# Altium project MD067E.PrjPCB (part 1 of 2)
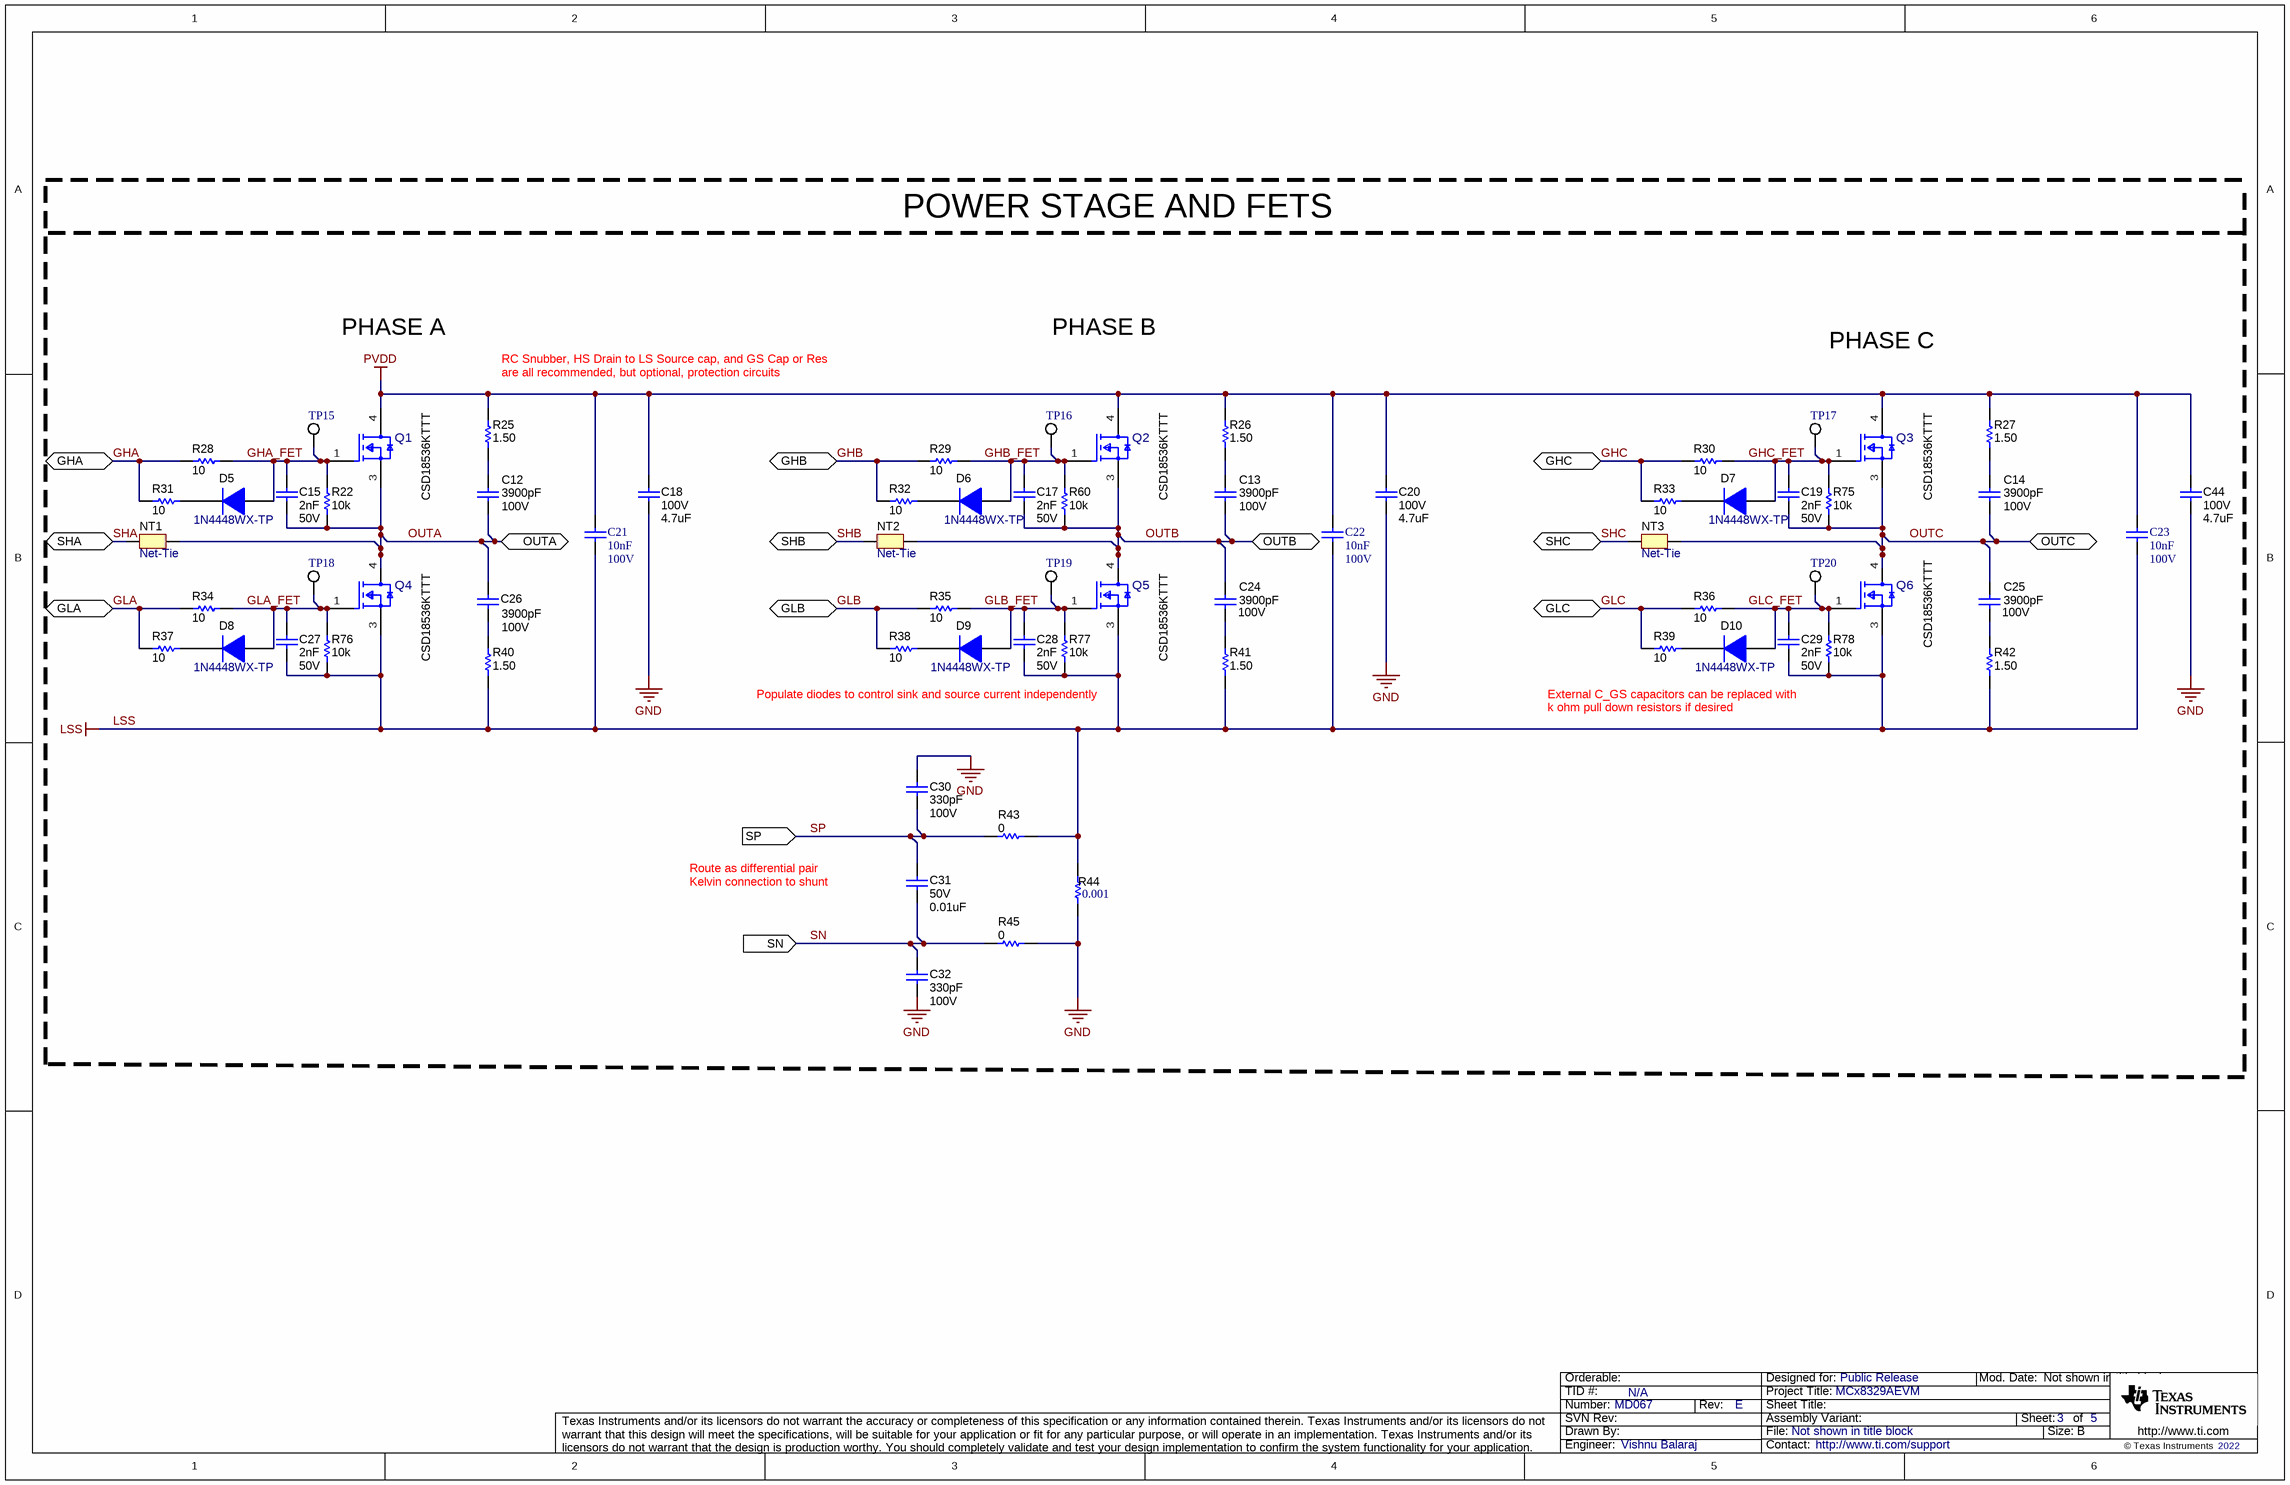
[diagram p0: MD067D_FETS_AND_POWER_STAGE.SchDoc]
TID: N/A; TechSupport: http://www.ti.com/support; SCH_Rev: E; PRJ_Title: MCx8329AEVM; PRJ_Number: MD067; PRJ_Engineer: Vishnu Balaraj; PRJ_Customer: Public Release; PCB_Rev: D; PCB_Layout: Vishnu Balaraj; CopyrightYear: 2022
5 sheets, 235 parts. Net scope: flat (ports and power ports of the same name join across sheets).
Board file: MD067D.PcbDoc
Sheets:
  MD067D_FETS_AND_POWER_STAGE.SchDoc
  MD067D_DRIVER.SchDoc
  MD067D_INTERFACE.SchDoc
  MD067D_HARDWARE.SchDoc
  MD067D_POWER_AND_CONNECTORS.SchDoc

## Sheet MD067D_FETS_AND_POWER_STAGE.SchDoc
size 431 x 279 mm; Date: Not shown in title block; ApprovedBy: Not shown in title block; CheckedBy: Not shown in title block; Author: Not shown in title block; CompanyName: Not shown in title block; Engineer: Not shown in title block; Organization: Not shown in title block; Address1: Not shown in title block; Address2: Not shown in title block; Address3: Not shown in title block; Address4: Not shown in title block; DocumentNumber: 3; Revision: Use project parameter SCH_Rev; SheetNumber: 3; SheetTotal: 5; PageSetup: Record=PageOptions¦CenterHorizontal=True¦CenterVertical=True¦PrintScale=1.00¦XCorrection=1.00¦YCorrection=1.00¦PrintKind=0¦BorderSize=5000000¦LeftOffset=0¦BottomOffset=0¦Orientation=2¦PaperLength=1000¦PaperWidth=1000¦Scale=100¦PaperSource=15¦PrintQuality=600¦MediaType=1¦DitherType=10¦PaperKind=Letter¦PrintScaleMode=1

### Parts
C12  VDC_V: 100V  ValueDisplayed: 3900pF  [1206L]  (hidden comment: 12061C392KAZ2A)
C13  VDC_V: 100V  ValueDisplayed: 3900pF  [1206L]  (hidden comment: 12061C392KAZ2A)
C14  VDC_V: 100V  ValueDisplayed: 3900pF  [1206L]  (hidden comment: 12061C392KAZ2A)
C15  Cap_F: 2nF  VDC_V: 50V  [0603L]  (hidden comment: GRM188R71H202KA01D)  (no BOM)
C17  Cap_F: 2nF  VDC_V: 50V  [0603L]  (hidden comment: GRM188R71H202KA01D)  (no BOM)
C18  VDC_V: 100V  ValueDisplayed: 4.7uF  [1210_220L]  (hidden comment: GRM32DC72A475KE01L)
C19  Cap_F: 2nF  VDC_V: 50V  [0603L]  (hidden comment: GRM188R71H202KA01D)  (no BOM)
C20  VDC_V: 100V  ValueDisplayed: 4.7uF  [1210_220L]  (hidden comment: GRM32DC72A475KE01L)
C21  Cap_F: 10nF  Rated Voltage (DC): 100V  [WCAP-CSGP_0805_L2W1.25H0.8_Reflow]  (hidden comment: 885012207122)
C22  Cap_F: 10nF  Rated Voltage (DC): 100V  [WCAP-CSGP_0805_L2W1.25H0.8_Reflow]  (hidden comment: 885012207122)
C23  Cap_F: 10nF  Rated Voltage (DC): 100V  [WCAP-CSGP_0805_L2W1.25H0.8_Reflow]  (hidden comment: 885012207122)
C24  VDC_V: 100V  ValueDisplayed: 3900pF  [1206L]  (hidden comment: 12061C392KAZ2A)
C25  VDC_V: 100V  ValueDisplayed: 3900pF  [1206L]  (hidden comment: 12061C392KAZ2A)
C26  VDC_V: 100V  ValueDisplayed: 3900pF  [1206L]  (hidden comment: 12061C392KAZ2A)
C27  Cap_F: 2nF  VDC_V: 50V  [0603L]  (hidden comment: GRM188R71H202KA01D)  (no BOM)
C28  Cap_F: 2nF  VDC_V: 50V  [0603L]  (hidden comment: GRM188R71H202KA01D)  (no BOM)
C29  Cap_F: 2nF  VDC_V: 50V  [0603L]  (hidden comment: GRM188R71H202KA01D)  (no BOM)
C30  Cap_F: 330pF  VDC_V: 100V  [0603L]  (hidden comment: 06031C331KAT2A)
C31  VDC_V: 50V  ValueDisplayed: 0.01uF  [0603L]  (hidden comment: C1608NP01H103J080AA)
C32  Cap_F: 330pF  VDC_V: 100V  [0603L]  (hidden comment: 06031C331KAT2A)
C44  VDC_V: 100V  ValueDisplayed: 4.7uF  [1210_220L]  (hidden comment: GRM32DC72A475KE01L)
D5  1N4448WX-TP  [SOD-323]
D6  1N4448WX-TP  [SOD-323]
D7  1N4448WX-TP  [SOD-323]
D8  1N4448WX-TP  [SOD-323]
D9  1N4448WX-TP  [SOD-323]
D10  1N4448WX-TP  [SOD-323]
NT1  Net-Tie  [Net-Tie_0805_HV_NoOverlay]  (net tie, no BOM)
NT2  Net-Tie  [Net-Tie_0805_HV_NoOverlay]  (net tie, no BOM)
NT3  Net-Tie  [Net-Tie_0805_HV_NoOverlay]  (net tie, no BOM)
Q1  CSD18536KTTT  [KTT0002A-MFG]
Q2  CSD18536KTTT  [KTT0002A-MFG]
Q3  CSD18536KTTT  [KTT0002A-MFG]
Q4  CSD18536KTTT  [KTT0002A-MFG]
Q5  CSD18536KTTT  [KTT0002A-MFG]
Q6  CSD18536KTTT  [KTT0002A-MFG]
R22  ValueDisplayed: 10k  [0603L]  (hidden comment: CRCW060310K0JNEA)
R25  ValueDisplayed: 1.50  [1206L]  (hidden comment: CRCW12061R50FKEA)
R26  ValueDisplayed: 1.50  [1206L]  (hidden comment: CRCW12061R50FKEA)
R27  ValueDisplayed: 1.50  [1206L]  (hidden comment: CRCW12061R50FKEA)
R28  ValueDisplayed: 10  [0603L]  (hidden comment: CRCW060310R0JNEA)
R29  ValueDisplayed: 10  [0603L]  (hidden comment: CRCW060310R0JNEA)
R30  ValueDisplayed: 10  [0603L]  (hidden comment: CRCW060310R0JNEA)
R31  ValueDisplayed: 10  [0603L]  (hidden comment: CRCW060310R0JNEA)
R32  ValueDisplayed: 10  [0603L]  (hidden comment: CRCW060310R0JNEA)
R33  ValueDisplayed: 10  [0603L]  (hidden comment: CRCW060310R0JNEA)
R34  ValueDisplayed: 10  [0603L]  (hidden comment: CRCW060310R0JNEA)
R35  ValueDisplayed: 10  [0603L]  (hidden comment: CRCW060310R0JNEA)
R36  ValueDisplayed: 10  [0603L]  (hidden comment: CRCW060310R0JNEA)
R37  ValueDisplayed: 10  [0603L]  (hidden comment: CRCW060310R0JNEA)
R38  ValueDisplayed: 10  [0603L]  (hidden comment: CRCW060310R0JNEA)
R39  ValueDisplayed: 10  [0603L]  (hidden comment: CRCW060310R0JNEA)
R40  ValueDisplayed: 1.50  [1206L]  (hidden comment: CRCW12061R50FKEA)
R41  ValueDisplayed: 1.50  [1206L]  (hidden comment: CRCW12061R50FKEA)
R42  ValueDisplayed: 1.50  [1206L]  (hidden comment: CRCW12061R50FKEA)
R43  ValueDisplayed: 0  [0603L]  (hidden comment: ERJ-3GEY0R00V)
R44  ValueDisplayed: 0.001  [CRE2512-R1_R4]  (hidden comment: CRE2512-FZ-R001E-3)
R45  ValueDisplayed: 0  [0603L]  (hidden comment: ERJ-3GEY0R00V)
R60  ValueDisplayed: 10k  [0603L]  (hidden comment: CRCW060310K0JNEA)
R75  ValueDisplayed: 10k  [0603L]  (hidden comment: CRCW060310K0JNEA)
R76  ValueDisplayed: 10k  [0603L]  (hidden comment: CRCW060310K0JNEA)
R77  ValueDisplayed: 10k  [0603L]  (hidden comment: CRCW060310K0JNEA)
R78  ValueDisplayed: 10k  [0603L]  (hidden comment: CRCW060310K0JNEA)
TP15  GHA_FET  [Testpoint_Keystone_Miniature]  (value not drawn)
TP16  GHB_FET  [Testpoint_Keystone_Miniature]  (value not drawn)
TP17  GHC_FET  [Testpoint_Keystone_Miniature]  (value not drawn)
TP18  GLA_FET  [Testpoint_Keystone_Miniature]  (value not drawn)
TP19  GLB_FET  [Testpoint_Keystone_Miniature]  (value not drawn)
TP20  GLC_FET  [Testpoint_Keystone_Miniature]  (value not drawn)

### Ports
GHA (bidir), GHB (bidir), GHC (bidir), GLA (bidir), GLB (bidir), GLC (bidir), OUTA (bidir), OUTB (bidir), OUTC (bidir), SHA (bidir), SHB (bidir), SHC (bidir), SN (in), SP (in)

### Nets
GND: C18.2 C20.2 C30.1 C32.2 C44.2 R44.1 R45.2
LSS: C21.1 C22.1 C23.1 C27.2 C28.2 C29.2 Q4.3(Source) Q5.3(Source) Q6.3(Source) R40.1 R41.1 R42.1 R43.2 R44.2 R76.1 R77.1 R78.1
PVDD: C18.1 C20.1 C21.2 C22.2 C23.2 C44.1 Q1.4(Drain) Q2.4(Drain) Q3.4(Drain) R25.1 R26.1 R27.1
GHA: R28.1 R31.1 ; port GHA
GHA_FET: C15.1 D5.2(A) Q1.1(Gate) R22.2 R28.2 TP15.1
GHB: R29.1 R32.1 ; port GHB
GHB_FET: C17.1 D6.2(A) Q2.1(Gate) R29.2 R60.2 TP16.1
GHC: R30.1 R33.1 ; port GHC
GHC_FET: C19.1 D7.2(A) Q3.1(Gate) R30.2 R75.2 TP17.1
GLA: R34.1 R37.1 ; port GLA
GLA_FET: C27.1 D8.2(A) Q4.1(Gate) R34.2 R76.2 TP18.1
GLB: R35.1 R38.1 ; port GLB
GLB_FET: C28.1 D9.2(A) Q5.1(Gate) R35.2 R77.2 TP19.1
GLC: R36.1 R39.1 ; port GLC
GLC_FET: C29.1 D10.2(A) Q6.1(Gate) R36.2 R78.2 TP20.1
OUTA: C12.1 C15.2 C26.1 NT1.2 Q1.3(Source) Q4.4(Drain) R22.1 ; port OUTA
OUTB: C13.1 C17.2 C24.1 NT2.2 Q2.3(Source) Q5.4(Drain) R60.1 ; port OUTB
OUTC: C14.1 C19.2 C25.1 NT3.2 Q3.3(Source) Q6.4(Drain) R75.1 ; port OUTC
SHA: NT1.1 ; port SHA
SHB: NT2.1 ; port SHB
SHC: NT3.1 ; port SHC
SN: C31.2 C32.1 R45.1 ; port SN
SP: C30.2 C31.1 R43.1 ; port SP
NetC12_2: C12.2 R25.2
NetC13_2: C13.2 R26.2
NetC14_2: C14.2 R27.2
NetC24_2: C24.2 R41.2
NetC25_2: C25.2 R42.2
NetC26_2: C26.2 R40.2
NetD5_1: D5.1(K) R31.2
NetD6_1: D6.1(K) R32.2
NetD7_1: D7.1(K) R33.2
NetD8_1: D8.1(K) R37.2
NetD9_1: D9.1(K) R38.2
NetD10_1: D10.1(K) R39.2

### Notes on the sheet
- POWER STAGE AND FETS
- PHASE A
- RC Snubber, HS Drain to LS Source cap, and GS Cap or Res
- PHASE B
- PHASE C
- (near R25) are all recommended, but optional, protection circuits
- Populate diodes to control sink and source current independently
- External C_GS capacitors can be replaced with
- k ohm pull down resistors if desired
- Route as differential pair
- Kelvin connection to shunt

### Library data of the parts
C12-C14 C24-C26 = CMP-0008756-2: CAP CER 3900PF 100V X7R 1206; Manufacturer: AVX Corporation; TaMin_C: -55°C; Polarized: N; SizeAreaWB_mm2: 10.92; Value1: Unknown; U/M: EA; TaMax_C: 125°C; Tolerance_%: 10%; SizeZ_mm: 1.35; SizeX_mm: 3.2; SizeY_mm: 1.6; Cap_Case: 1206; SizeArea_mm2: 5.12; Cap_F: 3.9nF; AEC Category: Q200
C15 C17 C19 C27-C29 = CMP-0007441-5: CAP, CERM, 2000 pF, 50 V, +/- 10%, X7R, 0603; Manufacturer: MuRata; TaMin_C: -55°C; Polarized: N; SizeAreaWB_mm2: 4.68; Value1: Unknown; U/M: EA; Value: 2000pF; TaMax_C: 125°C; SizeZ_mm: 1; SizeX_mm: 1.6; SizeY_mm: 0.8; Cap_Case: 0603; SizeArea_mm2: 1.28; AEC Category: Q200
C18 C20 C44 = CMP-0009182-2: CAP, CERM, 4.7 uF, 100 V, +/- 10%, X7S, 1210; Manufacturer: MuRata; TaMin_C: -55°C; Polarized: N; SizeAreaWB_mm2: 14.7; Value1: Unknown; U/M: EA; Value: 4.7uF; TaMax_C: 125°C; SizeZ_mm: 2.2; SizeX_mm: 3.2; SizeY_mm: 2.5; Cap_Case: 1210; SizeArea_mm2: 8; Cap_F: 4.7µF; AEC Category: Q200
C21-C23 = CMP-0108439-1: WCAP-CSGP Multilayer Ceramic Chip Capacitor, General Purpose, size 0805, X7R, 10nF, 100VDC; Manufacturer: Wurth Elektronik; Capacitance Tolerance: +/-10%; Case/Size Code: 0805; Dissipation Factor: 2.5%; Insulation Resistance: 10GOhm; Technical Reference: X7R0805103K100DFCT10000; Value: 0.01uF
C30 C32 = CMP-0006740-4: CAP, CERM, 330 pF, 100 V, +/- 10%, X7R, 0603; Manufacturer: AVX; TaMin_C: -55°C; ESR_ohm: 0.472; Polarized: N; SizeAreaWB_mm2: 4.68; Value1: 0.472 ohm; U/M: EA; Value: 330pF; TaMax_C: 125°C; SizeZ_mm: 1; SizeX_mm: 1.6; SizeY_mm: 0.8; Cap_Case: 0603; SizeArea_mm2: 1.28; AEC Category: Q200
C31 = CMP-0006998-4: CAP, CERM, 0.01 uF, 50 V, +/- 5%, C0G/NP0, 0603; Manufacturer: TDK; TaMin_C: -55°C; Polarized: N; SizeAreaWB_mm2: 4.68; Value1: Unknown; U/M: EA; Value: 0.01uF; TaMax_C: 150°C; SizeZ_mm: 1; SizeX_mm: 1.6; SizeY_mm: 0.8; Cap_Case: 0603; SizeArea_mm2: 1.28; Cap_F: 10nF; AEC Category: Q200
D5-D10 = CMP-0076911-2: Diode, Switching, 75 V, 0.25 A, SOD-323; Manufacturer: Micro Commercial Components; SizeArea_mm2: 3.645; TJmax_C: 150°C; Vr_V: 75V; SizeY_mm: 1.35; Value: 75V; SizeAreaWB_mm2: 8.695; Green_Lifecycle: Not Set; SizeX_mm: 2.7; AEC Category: Q101; Io_A: 250mA; Green_REACh: Incomplete; Value1: 0.25A; SizeZ_mm: 1.0
NT1-NT3 = CMP-0078142-2: Single point connection between nets.
Q1-Q6 = CMP-0092295-1: MOSFET 60-V, N channel NexFET power MOSFET, single D2PAK, 1.6 mOhm 3-DDPAK/TO-263 -55 to 175; Manufacturer: Texas Instruments; QgTyp_nC: 108nC @ 10V; Threshold Vgs Min: 1.4V; VdsMax_V: 1V; Standoff Height: 0mm; Rdson45_ohm: 1.3m; Reverse Recovery Time: 86ns; ChMode: False; Turn On Delay Time: 11ns; Typ Forward Diode Voltage: 0.9V; Transconductance: 312S; Threshold Vgs Max: 2.2V; Rthja Max: 62°C/W; Drain To Source Breakdown Voltage: 60V; Reverse Recovery Charge: 323nC; TJmax_C: +175°C; AEC Qualified: No; Power_W: 375W; Turn Off Delay Time: 24ns; Number Of Channels: 1; Vgs_V: 20V; SizeZ_mm: 4.95mm; Pulse Drain Current: 400A; IdsMax_A: 200A; Input Capacitace At Vds: 8790pF @ 30V
R22 R60 R75-R78 = CMP-0025701-2: RES, 10 k, 5%, 0.1 W, 0603; Manufacturer: Vishay-Dale; Power_W: 100mW; TempCo: 200 ppm/C; Value_Code: 10k0; U/M: EA; Value: 10k; EIA_Code: E24; SizeX_mm: 1.6; SizeY_mm: 0.8; SizeZ_mm: 1; Value2: 0.1W; SizeArea_mm2: 1.28; VDC_V: 75V; AEC Category: Q200
R25-R27 R40-R42 = CMP-0016763-3: RES, 1.50, 1%, 0.25 W, AEC-Q200 Grade 0, 1206; Manufacturer: Vishay-Dale; Power_W: 250mW; TempCo: 100 ppm/C; Value_Code: 1R50; Value: 1.50; EIA_Code: E96; Res_ohm: 1.5; SizeX_mm: 3.2; SizeY_mm: 1.6; SizeZ_mm: 1.35; Value2: 0.25W; SizeArea_mm2: 5.12; AEC Qualified: Y; VDC_V: 200V; AEC Category: Q200; AEC Grade: 0
R28-R39 = CMP-0025703-4: RES, 10, 5%, 0.1 W, AEC-Q200 Grade 0, 0603; Manufacturer: Vishay-Dale; Power_W: 100mW; TempCo: 200 ppm/C; Value_Code: 10R0; Value: 10; EIA_Code: E24; SizeX_mm: 1.6; SizeY_mm: 0.8; SizeZ_mm: 1; Value2: 0.1W; SizeArea_mm2: 1.28; AEC Qualified: Y; VDC_V: 75V; AEC Category: Q200; AEC Grade: 0
R43 R45 = CMP-0025874-4: RES, 0, 5%, 0.1 W, AEC-Q200 Grade 0, 0603; Manufacturer: Panasonic; Power_W: 100mW; TempCo: 600 ppm/C; Value_Code: 0000; Value: 0; EIA_Code: E24; SizeX_mm: 1.6; SizeY_mm: 0.8; SizeZ_mm: 1; Value2: 0.1W; SizeArea_mm2: 1.28; AEC Qualified: Y; VDC_V: 50V; AEC Category: Q200; SizeAreaWB_mm2: 4.68
R44 = CMP-0015748-2: RES, 0.001, 1%, 3 W, AEC-Q200 Grade 0, 2512; Manufacturer: Bourns; Power_W: 3W; TempCo: 50 ppm/C; Value_Code: 1L000; U/M: EA; Value: 0.001; EIA_Code: E96; Res_ohm: 1m; SizeX_mm: 6.45; SizeY_mm: 3.35; SizeZ_mm: 0.9; SizeArea_mm2: 21.6075; AEC Qualified: Y; AEC Grade: 0; AEC Category: Q200
TP15-TP20 = CMP-0055152-1: Test Point, Miniature, SMT; Manufacturer: Keystone; CNHeader: FALSE; Green_Lifecycle: Active; Green_REACh: Passed; CT: TRUE

## Sheet MD067D_DRIVER.SchDoc
size 431 x 279 mm; Date: Not shown in title block; ApprovedBy: Not shown in title block; CheckedBy: Not shown in title block; Author: Not shown in title block; CompanyName: Not shown in title block; Engineer: Not shown in title block; Organization: Not shown in title block; Address1: Not shown in title block; Address2: Not shown in title block; Address3: Not shown in title block; Address4: Not shown in title block; DocumentNumber: 2; Revision: Use project parameter SCH_Rev; SheetNumber: 2; SheetTotal: 5; PageSetup: Record=PageOptions¦CenterHorizontal=True¦CenterVertical=True¦PrintScale=1.00¦XCorrection=1.00¦YCorrection=1.00¦PrintKind=0¦BorderSize=5000000¦LeftOffset=0¦BottomOffset=0¦Orientation=2¦PaperLength=1000¦PaperWidth=1000¦Scale=100¦PaperSource=15¦PrintQuality=600¦MediaType=1¦DitherType=10¦PaperKind=Letter¦PrintScaleMode=1
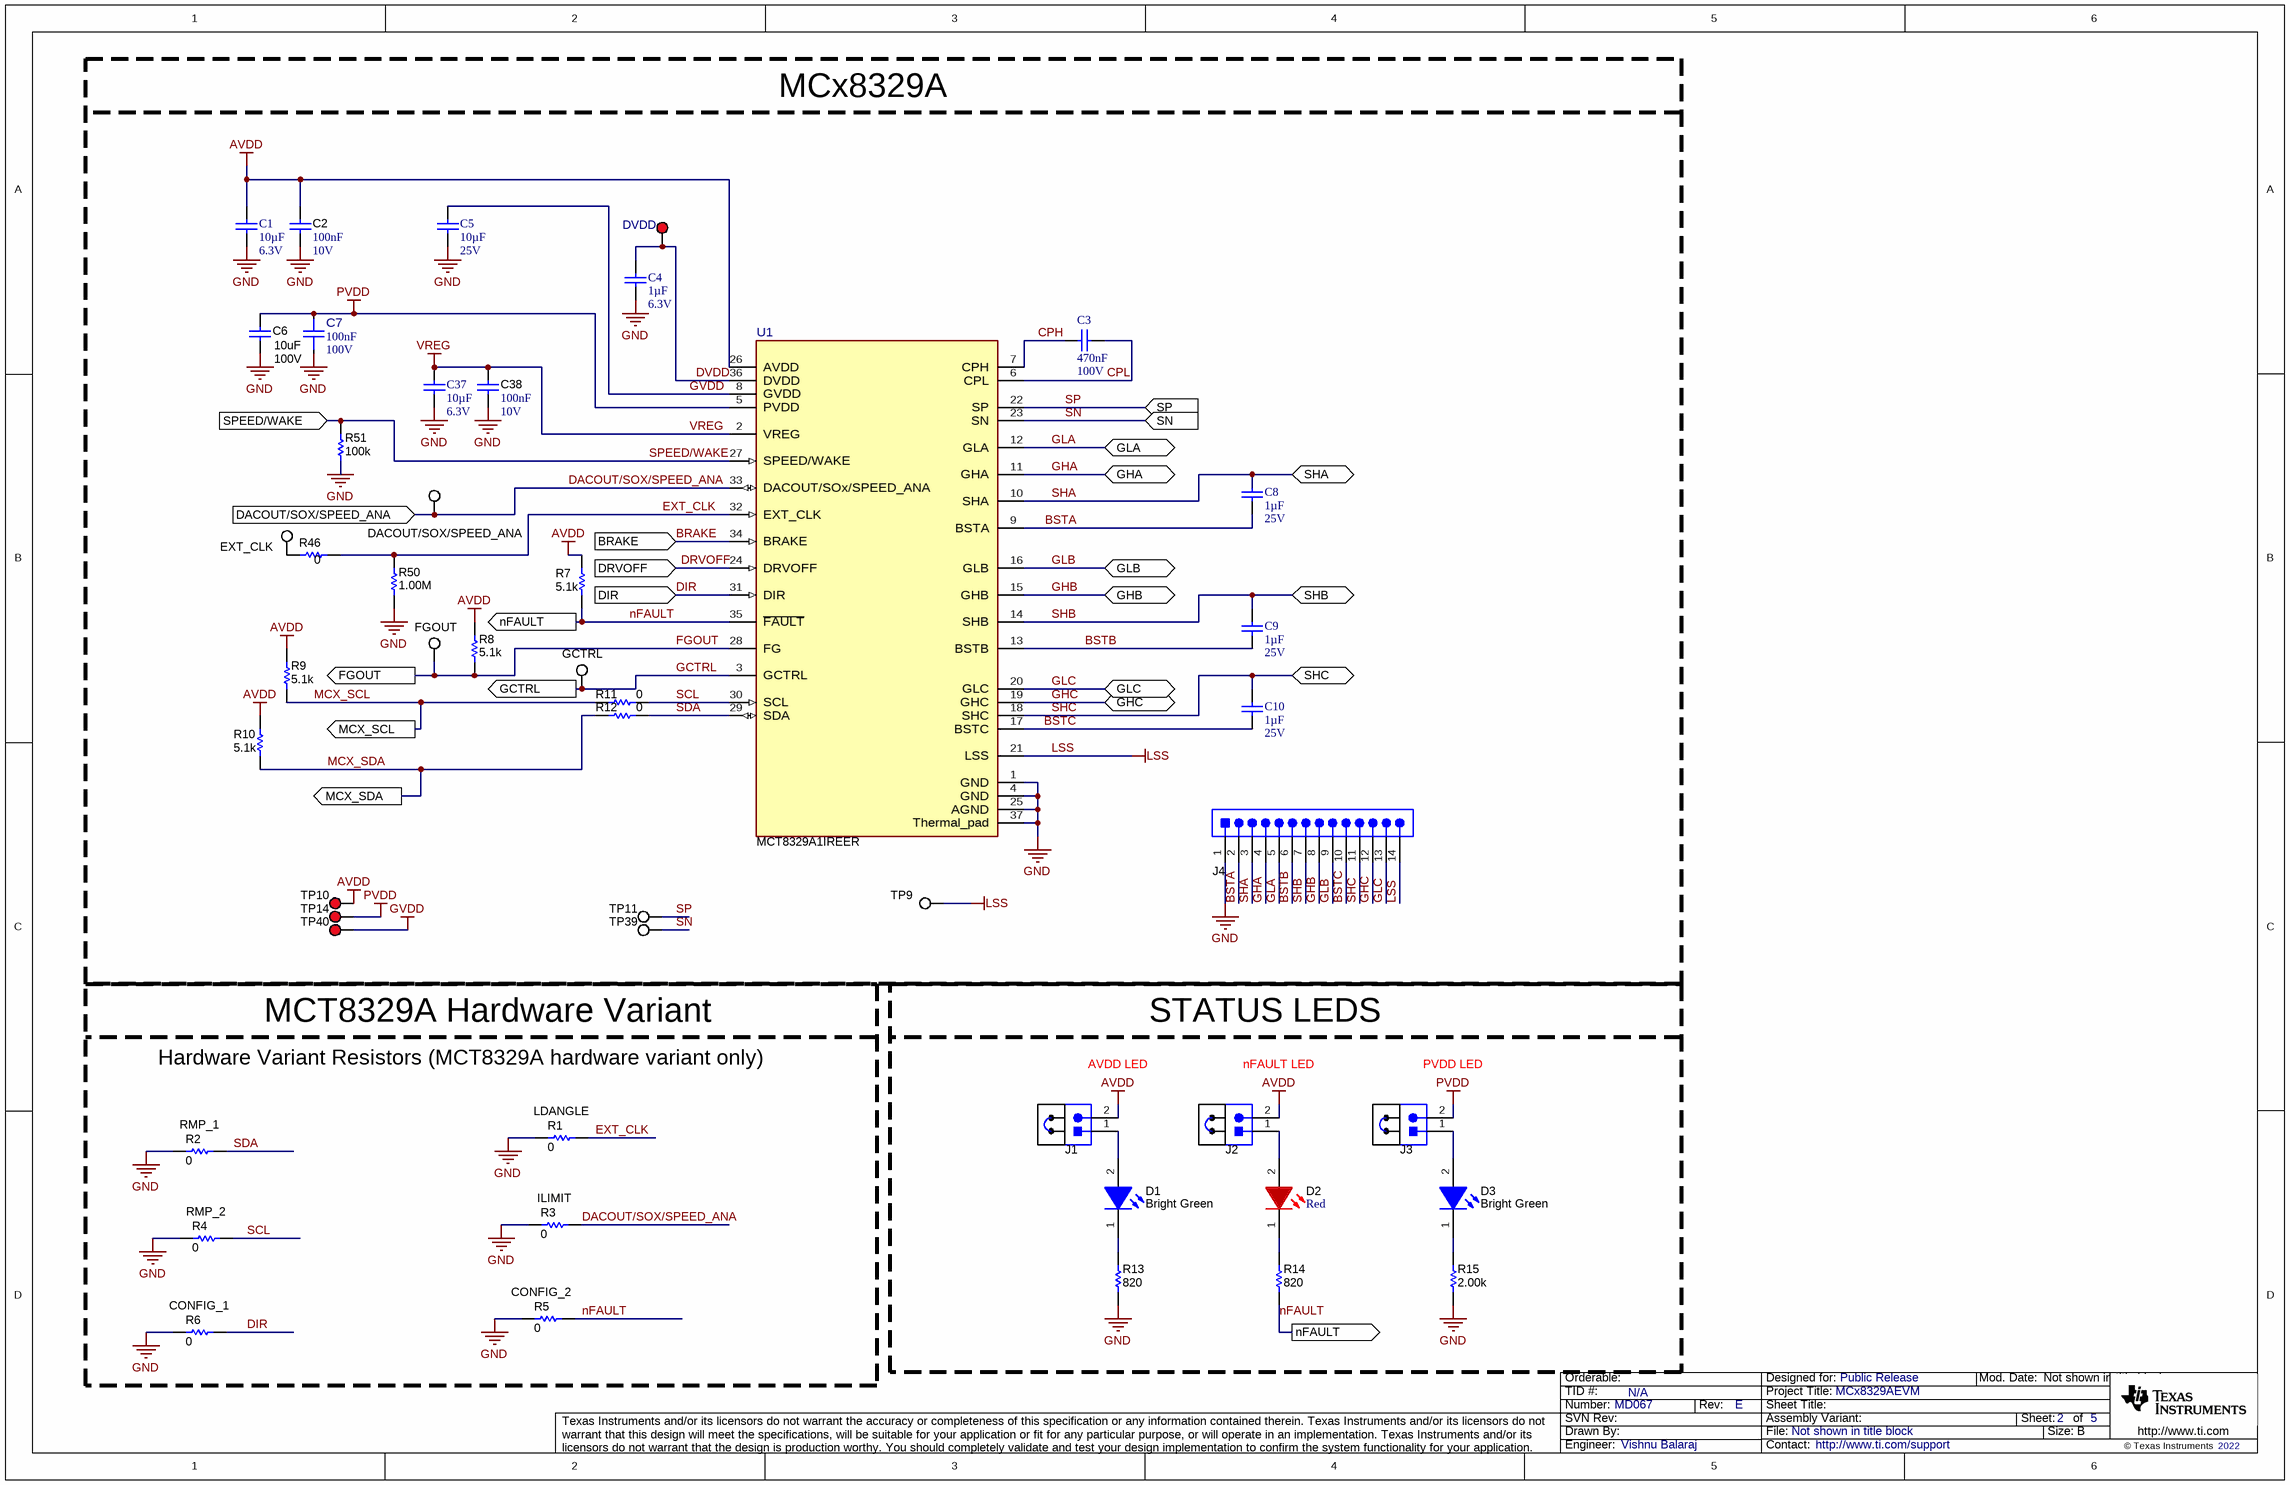
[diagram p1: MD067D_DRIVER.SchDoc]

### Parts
C1  Cap_F: 10µF  Rated Voltage (DC): 6.3V  [WCAP-CSGP_0603_L1.6W0.8H0.8_Reflow]  (hidden comment: 885012106006)
C2  Cap_F: 100nF  VDC_V: 10V  [0603]  (hidden comment: 885012206020)
C3  Cap_F: 470nF  Rated Voltage (DC): 100V  [WCAP-CSGP_0805_L2W1.25H1.25]  (hidden comment: 885012207130)
C4  Cap_F: 1µF  Rated Voltage (DC): 6.3V  [WCAP-CSGP_0603_L1.6W0.8H0.8_Reflow]  (hidden comment: 885012106003)
C5  Cap_F: 10µF  Rated Voltage (DC): 25V  [WCAP-CSGP_0603_L1.6W0.8H0.8_Reflow]  (hidden comment: 885012106031)
C6  VDC_V: 100V  ValueDisplayed: 10uF  [2220_280L]  (hidden comment: 22201C106MAT2A)
C7  Cap_F: 100nF  VDC_V: 100V  [FP-885012206120_0603-MFG]  (hidden comment: 885012206120)
C8  Cap_F: 1µF  Rated Voltage (DC): 25V  [WCAP-CSGP_0603_L1.6W0.8H0.8_Reflow]  (hidden comment: 885012106022)
C9  Cap_F: 1µF  Rated Voltage (DC): 25V  [WCAP-CSGP_0603_L1.6W0.8H0.8_Reflow]  (hidden comment: 885012106022)
C10  Cap_F: 1µF  Rated Voltage (DC): 25V  [WCAP-CSGP_0603_L1.6W0.8H0.8_Reflow]  (hidden comment: 885012106022)
C37  Cap_F: 10µF  Rated Voltage (DC): 6.3V  [WCAP-CSGP_0603_L1.6W0.8H0.8_Reflow]  (hidden comment: 885012106006)
C38  Cap_F: 100nF  VDC_V: 10V  [0603]  (hidden comment: 885012206020)
D1  value Bright Green  [WL-SMCW_Green_0805]  (hidden comment: 150080VS75000)
D2  value Red  [WL-SMCW_RED_0805]  (hidden comment: 150080RS75000)
D3  value Bright Green  [WL-SMCW_Green_0805]  (hidden comment: 150080VS75000)
J1  61300211121  [WURTH_61300211121]  (value not drawn)
J2  61300211121  [WURTH_61300211121]  (value not drawn)
J3  61300211121  [WURTH_61300211121]  (value not drawn)
J4  TSW-114-07-G-S  [TSW-114-07-G-S]  (value not drawn)
R1  ValueDisplayed: 0  [0603L]  (hidden comment: ERJ-3GEY0R00V)
R2  ValueDisplayed: 0  [0603L]  (hidden comment: ERJ-3GEY0R00V)
R3  ValueDisplayed: 0  [0603L]  (hidden comment: ERJ-3GEY0R00V)
R4  ValueDisplayed: 0  [0603L]  (hidden comment: ERJ-3GEY0R00V)
R5  ValueDisplayed: 0  [0603L]  (hidden comment: ERJ-3GEY0R00V)
R6  ValueDisplayed: 0  [0603L]  (hidden comment: ERJ-3GEY0R00V)
R7  ValueDisplayed: 5.1k  [0603L]  (hidden comment: CRCW06035K10JNEA)
R8  ValueDisplayed: 5.1k  [0603L]  (hidden comment: CRCW06035K10JNEA)
R9  ValueDisplayed: 5.1k  [0603L]  (hidden comment: CRCW06035K10JNEA)
R10  ValueDisplayed: 5.1k  [0603L]  (hidden comment: CRCW06035K10JNEA)
R11  ValueDisplayed: 0  [0603L]  (hidden comment: ERJ-3GEY0R00V)
R12  ValueDisplayed: 0  [0603L]  (hidden comment: ERJ-3GEY0R00V)
R13  ValueDisplayed: 820  [0603L]  (hidden comment: RC0603JR-07820RL)
R14  ValueDisplayed: 820  [0603L]  (hidden comment: RC0603JR-07820RL)
R15  ValueDisplayed: 2.00k  [0603L]  (hidden comment: RG1608P-202-B-T5)
R46  Res_ohm: 0  [0603]  (hidden comment: ERJ-3GEY0R00V)
R50  ValueDisplayed: 1.00M  [0603]  (hidden comment: RMCF0603FG1M00)
R51  ValueDisplayed: 100k  [0603]  (hidden comment: RT0603BRD07100KL)
SH-J1  60900213421  [Wurth_60900213421]  (value not drawn)
SH-J2  60900213421  [Wurth_60900213421]  (value not drawn)
SH-J3  60900213421  [Wurth_60900213421]  (value not drawn)
TP1  DVDD  [Keystone5000]
TP2  DACOUT/SOX/SPEED_ANA  [Keystone5002]
TP3  EXT_CLK  [Keystone5002]
TP4  FGOUT  [Keystone5002]
TP5  GCTRL  [Keystone5002]
TP9  LSS  [Testpoint_Keystone_Miniature]  (value not drawn)
TP10  AVDD  [Keystone5000]  (value not drawn)
TP11  SP  [Testpoint_Keystone_Miniature]  (value not drawn)
TP14  PVDD  [Keystone5000]  (value not drawn)
TP39  SN  [Testpoint_Keystone_Miniature]  (value not drawn)
TP40  GVDD  [Keystone5000]  (value not drawn)
U1  MCT8329A1IREER  [REE0036A-MFG]

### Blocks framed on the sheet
MCx8329A: C1-C10 C37 C38 J4 R7-R12 R46 R50 R51 TP1-TP5 TP9-TP11 TP14 TP39 TP40 U1
MCT8329A Hardware Variant: R1-R6
STATUS LEDS: D1-D3 J1-J3 R13-R15 SH-J1-SH-J3

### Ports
BRAKE (in), DACOUT/SOX/SPEED_ANA (in), DIR (in), DRVOFF (in), FGOUT (out), GCTRL (out), GHA (bidir), GHB (bidir), GHC (bidir), GLA (bidir), GLB (bidir), GLC (bidir), MCX_SCL (out), MCX_SDA (out), nFAULT (out), SHA (bidir), SHB (bidir), SHC (bidir), SN (in), SP (in), SPEED/WAKE (in)

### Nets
AVDD: C1.2 C2.2 J1.2 J2.2 R7.1 R8.2 R9.2 R10.2 TP10.1 U1.26(AVDD)
GND: C1.1 C2.1 C4.1 C5.1 C6.2 C7.1 C37.1 C38.2 J4.1 R1.2 R2.2 R3.2 R4.2 R5.2 R6.2 R13.1 R15.1 R50.1 R51.1 U1.1(GND) U1.4(GND) U1.25(AGND) U1.37(Thermal_pad)
GVDD: C5.2 TP40.1 U1.8(GVDD)
LSS: J4.14 TP9.1 U1.21(LSS)
PVDD: C6.1 C7.2 J3.2 TP14.1 U1.5(PVDD)
VREG: C37.2 C38.1 U1.2(VREG)
BRAKE: U1.34(BRAKE) ; port BRAKE
BSTA: C8.1 J4.2 U1.9(BSTA)
BSTB: C9.2 J4.6 U1.13(BSTB)
BSTC: C10.2 J4.10 U1.17(BSTC)
CPH: C3.2 U1.7(CPH)
CPL: C3.1 U1.6(CPL)
DACOUT/SOX/SPEED_ANA: R3.1 TP2.1 U1.33(DACOUT/SOx/SPEED_ANA) ; port DACOUT/SOX/SPEED_ANA
DIR: R6.1 U1.31(DIR) ; port DIR
DRVOFF: U1.24(DRVOFF) ; port DRVOFF
DVDD: C4.2 TP1.1 U1.36(DVDD)
EXT_CLK: R1.1 R46.2 R50.2 U1.32(EXT_CLK)
FGOUT: R8.1 TP4.1 U1.28(FG) ; port FGOUT
GCTRL: TP5.1 U1.3(GCTRL) ; port GCTRL
GHA: J4.4 U1.11(GHA) ; port GHA
GHB: J4.8 U1.15(GHB) ; port GHB
GHC: J4.12 U1.19(GHC) ; port GHC
GLA: J4.5 U1.12(GLA) ; port GLA
GLB: J4.9 U1.16(GLB) ; port GLB
GLC: J4.13 U1.20(GLC) ; port GLC
MCX_SCL: R9.1 R11.1 ; port MCX_SCL
MCX_SDA: R10.1 R12.1 ; port MCX_SDA
nFAULT: R5.1 R7.2 R14.1 U1.35(~{FAULT}) ; port nFAULT
SCL: R4.1 R11.2 U1.30(SCL)
SDA: R2.1 R12.2 U1.29(SDA)
SHA: C8.2 J4.3 U1.10(SHA) ; port SHA
SHB: C9.1 J4.7 U1.14(SHB) ; port SHB
SHC: C10.1 J4.11 U1.18(SHC) ; port SHC
SN: TP39.1 U1.23(SN) ; port SN
SP: TP11.1 U1.22(SP) ; port SP
SPEED/WAKE: R51.2 U1.27(SPEED/WAKE) ; port SPEED/WAKE
NetD1_1: D1.1(K) R13.2
NetD1_2: D1.2(A) J1.1
NetD2_1: D2.1(K) R14.2
NetD2_2: D2.2(A) J2.1
NetD3_1: D3.1(K) R15.2
NetD3_2: D3.2(A) J3.1
NetR46_1: R46.1 TP3.1

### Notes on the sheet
- Hardware Variant Resistors (MCT8329A hardware variant only)
- (near R1) LDANGLE
- AVDD LED
- nFAULT LED
- PVDD LED
- (near R2) RMP_1
- (near R4) RMP_2
- (near R3) ILIMIT
- (near R6) CONFIG_1
- (near R5) CONFIG_2

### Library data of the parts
C1 = CMP-0108062-1: WCAP-CSGP Multilayer Ceramic Chip Capacitor, General Purpose, size 0603, X5R, 10µF, 6.3VDC; Manufacturer: Wurth Elektronik; Capacitance Tolerance: +/-20%; Case/Size Code: 0603; Dissipation Factor: 10%; Insulation Resistance: 0.01GOhm; Technical Reference: X5R0603106M6R3DFCT10000; Value: 10uF
C2 C38 = CMP-0064931-4: CAP, CERM, 0.1 uF, 10 V,+/- 10%, X7R, 0603; Manufacturer: Wurth Elektronik; TaMin_C: -55°C; Polarized: N; SizeAreaWB_mm2: 4.68; Value1: Unknown; U/M: EA; Value: 0.1uF; TaMax_C: 125°C; SizeZ_mm: 1; SizeX_mm: 1.6; SizeY_mm: 0.8; SizeArea_mm2: 1.28; AEC Category: Q200
C3 = CMP-0115615-1: WCAP-CSGP Multilayer Ceramic Chip Capacitor, General Purpose, size 0805, X7R Class II, 470nF, 100VDC; Manufacturer: Wurth Elektronik; Capacitance Tolerance: +/-10%; Case/Size Code: 0805; Dissipation Factor: 10%; Insulation Resistance: 0.2GOhm; Technical Reference: X7R0805474K100DFCT10000
C4 = CMP-0111654-1: WCAP-CSGP Multilayer Ceramic Chip Capacitor, General Purpose, size 0603, X5R, 1µF, 6.3VDC; Manufacturer: Wurth Elektronik; Capacitance Tolerance: +/-20%; Case/Size Code: 0603; Dissipation Factor: 10%; Insulation Resistance: 0.1GOhm; Technical Reference: X5R0603105M6R3DFCT10000; Value: 1uF
C5 = CMP-0111676-1: WCAP-CSGP Multilayer Ceramic Chip Capacitor, General Purpose, size 0603, X5R, 10µF, 25VDC; Manufacturer: Wurth Elektronik; Capacitance Tolerance: +/20%; Value: 10uF; Dissipation Factor: 20%; Insulation Resistance: 0.01GOhm; Technical Reference: X5R0603106M025DFCT10000
C6 = CMP-0009304-2: CAP, CERM, 10 uF, 100 V, +/- 20%, X7R, 2220; Manufacturer: AVX; TaMin_C: -55°C; Polarized: N; SizeAreaWB_mm2: 53.9; Value1: Unknown; U/M: EA; Value: 10uF; TaMax_C: 125°C; SizeZ_mm: 2.8; SizeX_mm: 5.7; SizeY_mm: 5; Cap_Case: 2220; SizeArea_mm2: 28.5; Cap_F: 10µF; AEC Category: Q200
C7 = CMP-0097294-1: 0.1 µF ±10% 100V Ceramic Capacitor X7R 0603 (1608 Metric); Manufacturer: Wurth Electronics; TempCo: 15%; Value: 100nF; SizeZ_mm: 0.87mm; AEC Qualified: No
C8-C10 = CMP-0104504-1: WCAP-CSGP Multilayer Ceramic Chip Capacitor, General Purpose, size 0603, X5R, 1µF, 25VDC; Manufacturer: Wurth Elektronik; Capacitance Tolerance: +/-20%; Case/Size Code: 0603; Dissipation Factor: 10%; Insulation Resistance: 0.5GOhm; Technical Reference: X5R0603105M025DFCT10000; Value: 1uF
C37 = CMP-0108062-1: WCAP-CSGP Multilayer Ceramic Chip Capacitor, General Purpose, size 0603, X5R, 10µF, 6.3VDC; Manufacturer: Wurth Elektronik; Capacitance Tolerance: +/-20%; Value: 10uF; Dissipation Factor: 10%; Insulation Resistance: 0.01GOhm; Technical Reference: X5R0603106M6R3DFCT10000
D1 D3 = CMP-0002960-2: LED, Bright Green, SMD; Manufacturer: Wurth Elektronik; Io_A: 20mA; Value1: 0.072W; Vf_V: 2V; Type: AlInGaP; Angle: 140; Power_TotalModule: 72mW; Tjmax_C: 85°C; Vr_V: 5V; U/M: EA
D2 = CMP-0077509-2: LED, Red, SMD; Manufacturer: Wurth Elektronik; Io_A: 20mA; Value1: 0.072W; Vf_V: 2V; Type: AlInGaP; Angle: 140.0; Ir_A: 10µA; Power_TotalModule: 72mW; Vr_V: 5V
J1-J3 = CMP-0054794-2: Header, 2.54 mm, 2x1, Gold, TH; Manufacturer: Wurth Elektronik; Green_Lifecycle: Active; Pitch_mm: 2.54; Green_REACh: Passed; Row_Count: 1; Gender: Male; Shrouded: N; Cert_UL: Y
J4 = CMP-0075428-1: Header, 100mil, 14x1, Gold, TH; Manufacturer: Samtec; Voltage_V: 550V; Current_A: 6.3A; Row_Count: 1; Cert_CSA: Y; Cert_CULUS: N; CNHeader: True; CT: False; Gender: Male; Green_Lifecycle: Active; Green_REACh: Passed; Pitch_mm: 2.54
R1-R6 R11 R12 R46 = CMP-0025874-4: as R43 on sheet MD067D_FETS_AND_POWER_STAGE
R7-R10 = CMP-0025830-4: RES, 5.1 k, 5%, 0.1 W, AEC-Q200 Grade 0, 0603; Manufacturer: Vishay-Dale; Power_W: 100mW; TempCo: 200 ppm/C; Value_Code: 5k10; Value: 5.1k; EIA_Code: E24; SizeX_mm: 1.6; SizeY_mm: 0.8; SizeZ_mm: 1; Value2: 0.1W; SizeArea_mm2: 1.28; AEC Qualified: Y; VDC_V: 75V; AEC Category: Q200; AEC Grade: 0
R13 R14 = CMP-0025941-5: RES, 820, 5%, 0.1 W, 0603; Manufacturer: Yageo; Power_W: 100mW; TempCo: 100 ppm/C; Value_Code: 820R; Value: 820; EIA_Code: E24; SizeX_mm: 1.6; SizeY_mm: 0.8; SizeZ_mm: 1; Value2: 0.1W; SizeArea_mm2: 1.28; AEC Qualified: N; VDC_V: 75V; AEC Category: Q200; SizeAreaWB_mm2: 4.68
R15 = CMP-0023463-3: RES, 2.00 k, 0.1%, 0.1 W, 0603; Manufacturer: Susumu Co Ltd; Power_W: 100mW; TempCo: 25 ppm/C; Value_Code: 2k00; U/M: EA; Value: 2.00k; EIA_Code: E192; Res_ohm: 2k; SizeX_mm: 1.6; SizeY_mm: 0.8; SizeZ_mm: 1; Value2: 0.1W; SizeArea_mm2: 1.28; VDC_V: 75V; AEC Category: Q200
R50 = CMP-0085900-1: RES, 1.00 M, 1%, 0.1 W, AEC-Q200 Grade 0, 0603; Manufacturer: Stackpole Electronics Inc; AEC Category: Q200; Res_ohm: 1M; SizeX_mm: 1.6; SizeY_mm: 0.8; Value: 1.00Meg; SizeAreaWB_mm2: 4.68; SizeArea_mm2: 1.28; Power_W: 100mW; AEC Qualified: Y; EIA_Code: E96; AEC Grade: 0; Value_Code: 1M00; Value2: 0.1W; TempCo: 100 ppm/C; SizeZ_mm: 1
R51 = CMP-0023630-1: RES, 100 k, 0.1%, 0.1 W, 0603; Manufacturer: Yageo America; Power_W: 100mW; TempCo: 25 ppm/C; U/M: EA; Value: 100k; EIA_Code: E192; SizeX_mm: 1.6; SizeY_mm: 0.8; SizeZ_mm: 1; Value2: 0.1W; SizeArea_mm2: 1.28; VDC_V: 75V; AEC Category: Q200
SH-J1-SH-J3 = CMP-0003761-2: Shunt, 2.54mm, Gold, Black; Manufacturer: Wurth Elektronik; Value: 1x2
TP1 TP10 TP14 TP40 = CMP-0055137-1: Test Point, Miniature, Red, TH; PartNumber: 5000; Manufacturer: Keystone; ContactFinish: Silver; CNHeader: FALSE; CT: TRUE; Green_Lifecycle: Active; Green_REACh: Passed
TP2-TP5 = CMP-0055139-1: Test Point, Miniature, White, TH; Manufacturer: Keystone; CNHeader: FALSE; Green_Lifecycle: Active; Green_REACh: Passed; ContactFinish: Silver; CT: TRUE
TP9 TP11 TP39 = CMP-0055152-1: as TP15 on sheet MD067D_FETS_AND_POWER_STAGE
U1 = CMP-0095893-1: High Speed Sensorless Trapezoidal Control 4.5 to 60 V Three-phase BLDC Gate Driver; Manufacturer: Texas Instruments; Number Of Outputs: 3; AEC Qualified: No; Standoff Height: 0mm; Min Supply Voltage: 4.5V; Motor Type: Brushless DC; SizeZ_mm: 0.8mm; TaMin_C: -40°C; Switching Frequency: 100kHz; TJmax_C: +150°C; Max Supply Voltage: 60V; TaMax_C: +125°C

## Sheet MD067D_INTERFACE.SchDoc
size 431 x 279 mm; Date: Not shown in title block; ApprovedBy: Not shown in title block; CheckedBy: Not shown in title block; Author: Not shown in title block; CompanyName: Not shown in title block; Engineer: Not shown in title block; Organization: Not shown in title block; Address1: Not shown in title block; Address2: Not shown in title block; Address3: Not shown in title block; Address4: Not shown in title block; DocumentNumber: 1; Revision: Use project parameter SCH_Rev; SheetNumber: 1; SheetTotal: 5; PageSetup: Record=PageOptions¦CenterHorizontal=True¦CenterVertical=True¦PrintScale=1.00¦XCorrection=1.00¦YCorrection=1.00¦PrintKind=0¦BorderSize=5000000¦LeftOffset=0¦BottomOffset=0¦Orientation=2¦PaperLength=1000¦PaperWidth=1000¦Scale=100¦PaperSource=15¦PrintQuality=600¦MediaType=1¦DitherType=10¦PaperKind=Letter¦PrintScaleMode=1
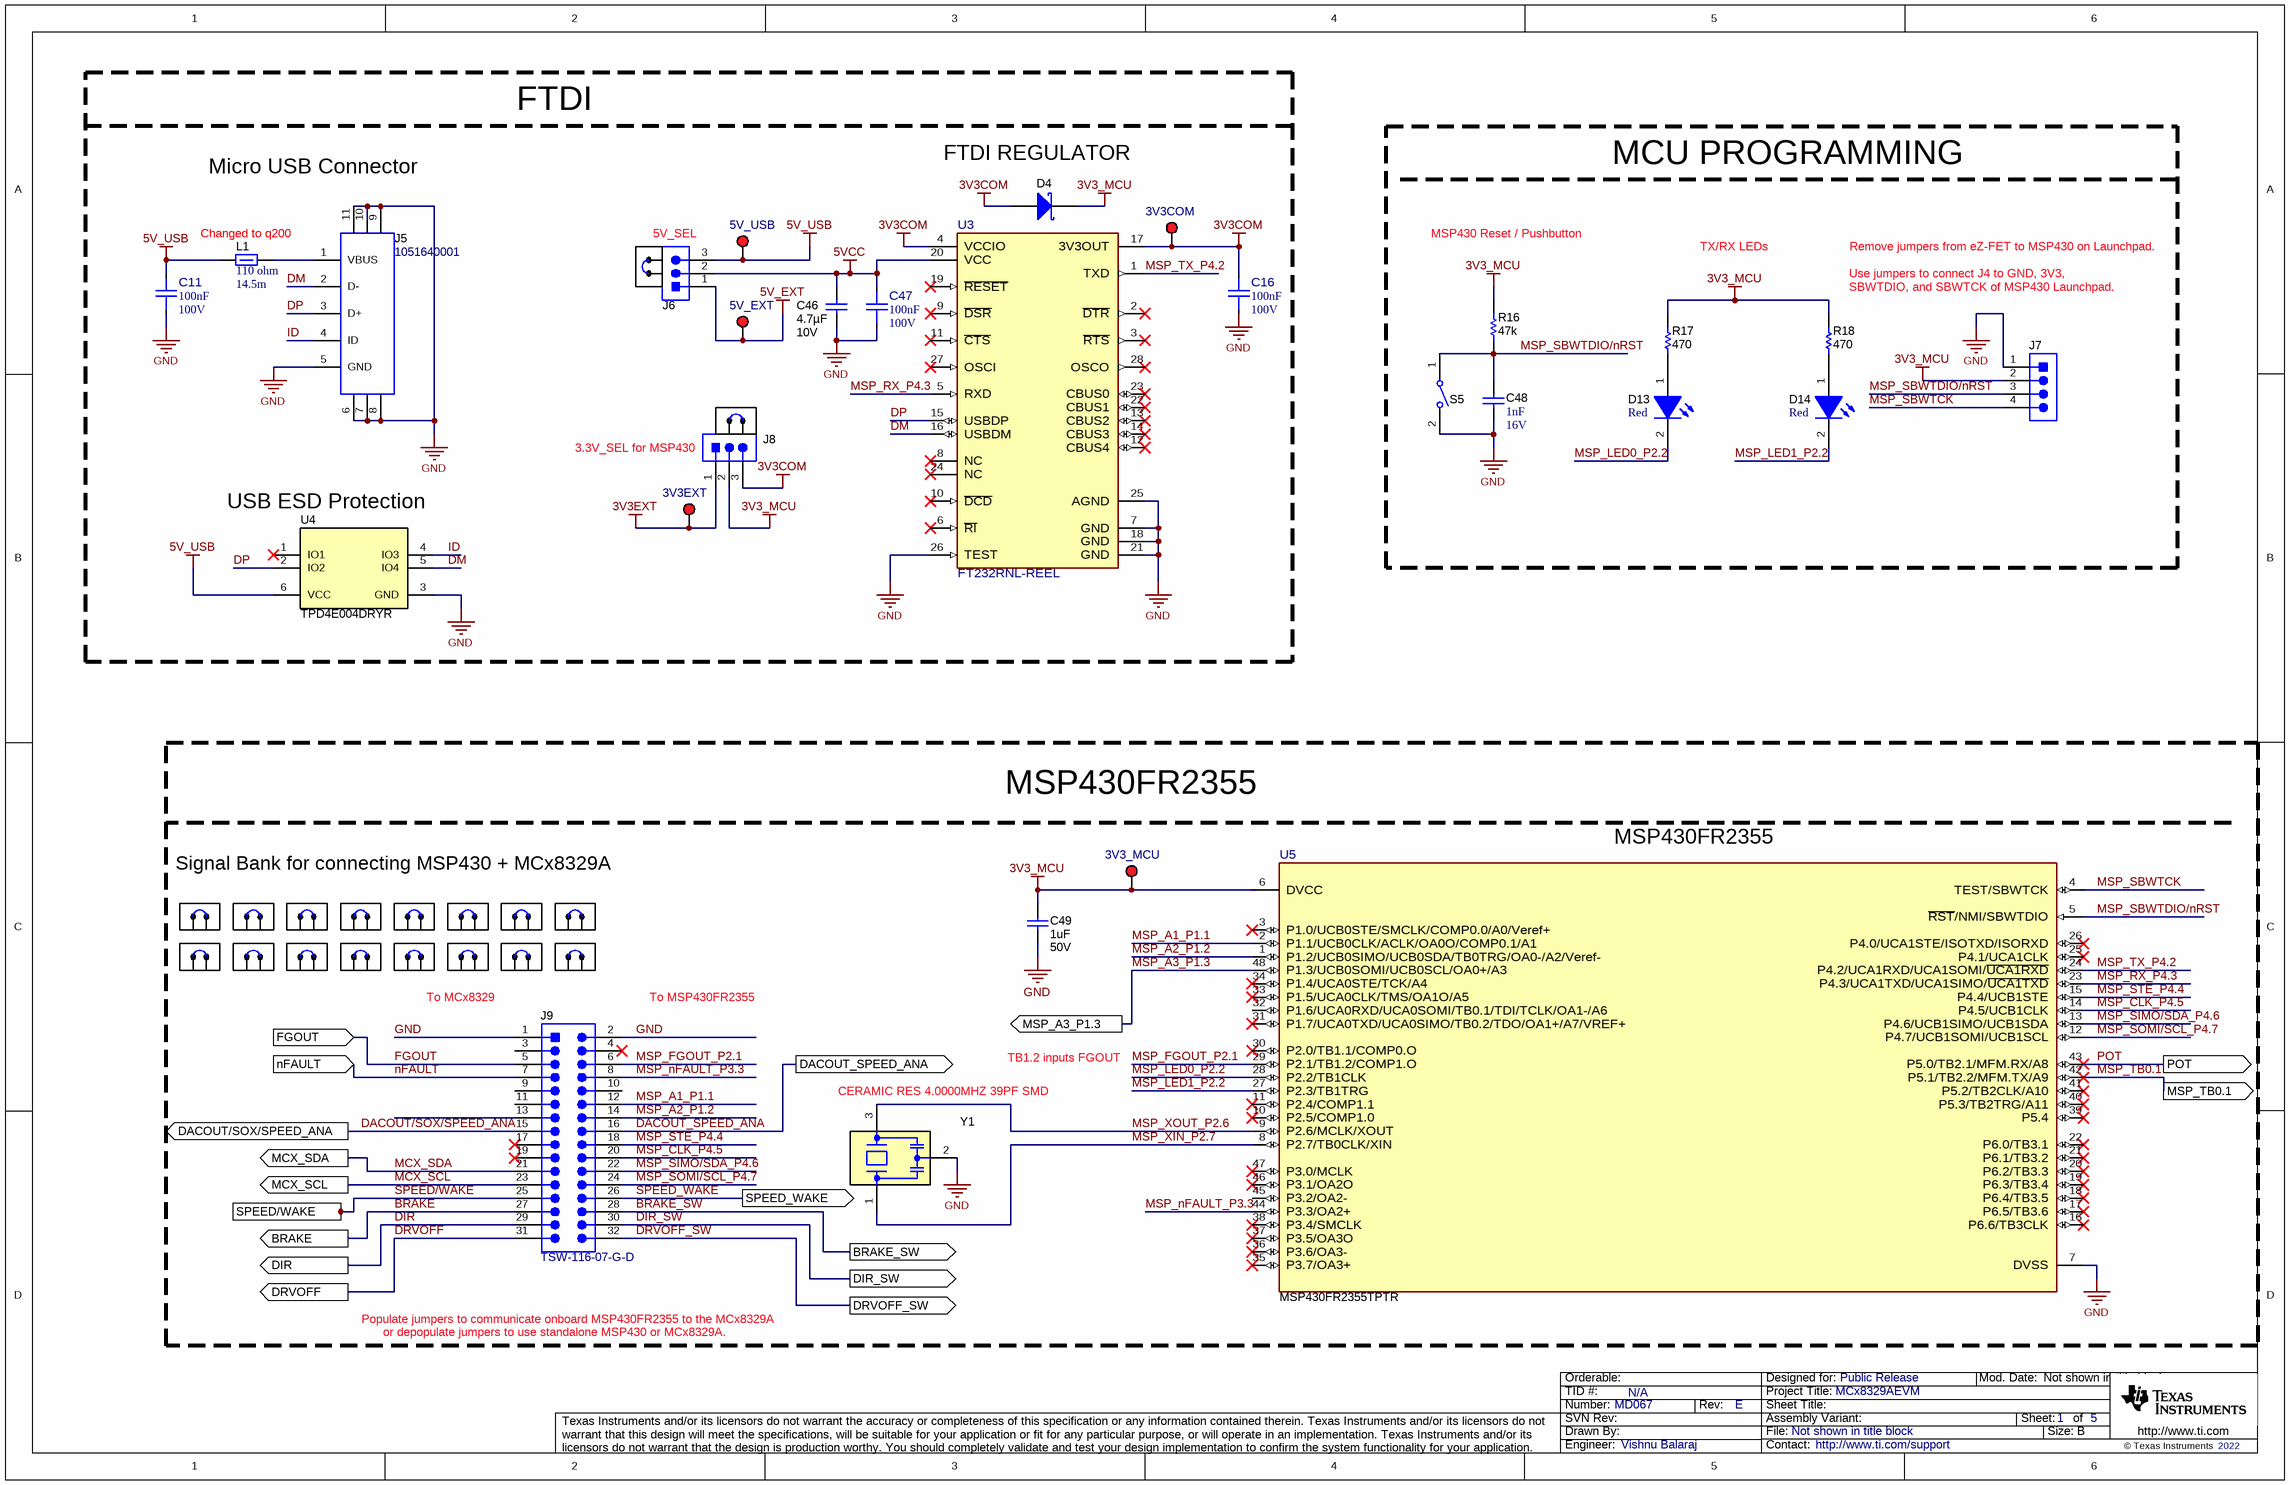
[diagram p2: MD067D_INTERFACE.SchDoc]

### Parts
C11  Cap_F: 100nF  VDC_V: 100V  [FP-885012206120_0603-MFG]  (hidden comment: 885012206120)
C16  Cap_F: 100nF  VDC_V: 100V  [FP-885012206120_0603-MFG]  (hidden comment: 885012206120)
C46  Cap_F: 4.7µF  VDC_V: 10V  [0603L]  (hidden comment: GRM188Z71A475ME15D)
C47  Cap_F: 100nF  VDC_V: 100V  [FP-885012206120_0603-MFG]  (hidden comment: 885012206120)
C48  Cap_F: 1nF  VDC_V: 16V  [0603L]  (hidden comment: 885012206034)
C49  ValueDisplayed: 1uF  VDC_V: 50V  [0805L]  (hidden comment: 885012207103)
D4  BAT165E6327HTSA1  [SOD-323]  (value not drawn)
D13  Color: Red  [FP-150060RS75003_0603-MFG]  (hidden comment: 150060RS75003)
D14  Color: Red  [FP-150060RS75003_0603-MFG]  (hidden comment: 150060RS75003)
J5  1051640001  [Molex_1051640001]
J6  61300311121  [WURTH_61300311121]  (value not drawn)
J7  61300411121  [WURTH_61300411121]  (value not drawn)
J8  61300311121  [WURTH_61300311121]  (value not drawn)
J9  TSW-116-07-G-D  [TSW-116-07-G-D]
L1  ValueDisplayed: 110 ohm  DCR_ohm: 14.5m  [0603]  (hidden comment: 74279228111)
R16  ValueDisplayed: 47k  [0603L]  (hidden comment: RC0603JR-0747KL)
R17  ValueDisplayed: 470  [0603L]  (hidden comment: RC0603JR-07470RL)
R18  ValueDisplayed: 470  [0603L]  (hidden comment: RC0603JR-07470RL)
S5  SW_SPST-single  [SW_434121025816]  (value not drawn)
SH-J4  60900213421  [Wurth_60900213421]  (value not drawn)
SH-J5  60900213421  [Wurth_60900213421]  (value not drawn)
SH-J6  60900213421  [Wurth_60900213421]  (value not drawn)
SH-J10  60900213421  [Wurth_60900213421]  (value not drawn)
SH-J11  60900213421  [Wurth_60900213421]  (value not drawn)
SH-J12  60900213421  [Wurth_60900213421]  (value not drawn)
SH-J13  60900213421  [Wurth_60900213421]  (value not drawn)
SH-J14  60900213421  [Wurth_60900213421]  (value not drawn)
SH-J15  60900213421  [Wurth_60900213421]  (value not drawn)
SH-J16  60900213421  [Wurth_60900213421]  (value not drawn)
SH-J17  60900213421  [Wurth_60900213421]  (value not drawn)
SH-J18  60900213421  [Wurth_60900213421]  (value not drawn)
SH-J19  60900213421  [Wurth_60900213421]  (value not drawn)
SH-J20  60900213421  [Wurth_60900213421]  (value not drawn)
SH-J21  60900213421  [Wurth_60900213421]  (value not drawn)
SH-J22  60900213421  [Wurth_60900213421]  (value not drawn)
SH-J23  60900213421  [Wurth_60900213421]  (value not drawn)
SH-J24  60900213421  [Wurth_60900213421]  (value not drawn)
TP41  3V3COM  [Keystone5000]
TP42  5V_USB  [Keystone5000]
TP43  5V_EXT  [Keystone5000]
TP44  3V3EXT  [Keystone5000]
TP45  3V3_MCU  [Keystone5000]
U3  FT232RNL-REEL  [FP-FT232RNL-REEL_SSOP28-MFG]
U4  TPD4E004DRYR  [DRY0006A]
U5  MSP430FR2355TPTR  [PT0048A-MFG]
Y1  CSTCR4M00G55B-R0  [Murata_CSTCR_G]  (value not drawn)

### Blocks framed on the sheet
FTDI: C11 C16 C46 C47 D4 J5 J6 J8 L1 SH-J4 SH-J5 TP41-TP44 U3 U4
MCU PROGRAMMING: C48 D13 D14 J7 R16-R18 S5
MSP430FR2355: C49 J9 SH-J6 SH-J10-SH-J24 TP45 U5 Y1

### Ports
BRAKE (out), BRAKE_SW (out), DACOUT/SOX/SPEED_ANA (out), DACOUT_SPEED_ANA (out), DIR (out), DIR_SW (out), DRVOFF (out), DRVOFF_SW (out), FGOUT (in), MCX_SCL (out), MCX_SDA (out), MSP_A3_P1.3 (out), MSP_TB0.1 (out), nFAULT (in), POT (out), SPEED/WAKE (out), SPEED_WAKE (out)

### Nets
3V3_MCU: C49.1 D4.1(K) J7.2 J8.2 R16.2 R17.2 R18.2 TP45.1 U5.6(DVCC)
3V3COM: C16.2 D4.2(A) J8.3 TP41.1 U3.4(VCCIO) U3.17(3V3OUT)
3V3EXT: J8.1 TP44.1
5V_EXT: J6.1 TP43.1
5V_USB: C11.2 J6.3 L1.1 TP42.1 U4.6(VCC)
5VCC: C46.2 C47.2 J6.2 U3.20(VCC)
GND: C11.1 C16.1 C46.1 C47.1 C48.2 C49.2 J5.5(GND) J5.6 J5.7 J5.8 J5.9 J5.10 J5.11 J7.1 J9.1 J9.2 S5.2 U3.7(GND) U3.18(GND) U3.21(GND) U3.25(AGND) U3.26(TEST) U4.3(GND) U5.7(DVSS) Y1.2(GND)
BRAKE: J9.27 ; port BRAKE
BRAKE_SW: J9.28 ; port BRAKE_SW
DACOUT/SOX/SPEED_ANA: J9.15 ; port DACOUT/SOX/SPEED_ANA
DACOUT_SPEED_ANA: J9.16 ; port DACOUT_SPEED_ANA
DIR: J9.29 ; port DIR
DIR_SW: J9.30 ; port DIR_SW
DM: J5.2(D-) U3.16(USBDM) U4.5(IO4)
DP: J5.3(D+) U3.15(USBDP) U4.2(IO2)
DRVOFF: J9.31 ; port DRVOFF
DRVOFF_SW: J9.32 ; port DRVOFF_SW
FGOUT: J9.5 ; port FGOUT
ID: J5.4(ID) U4.4(IO3)
MCX_SCL: J9.23 ; port MCX_SCL
MCX_SDA: J9.21 ; port MCX_SDA
MSP_A1_P1.1: J9.12 U5.2(P1.1/UCB0CLK/ACLK/OA0O/COMP0.1/A1)
MSP_A2_P1.2: J9.14 U5.1(P1.2/UCB0SIMO/UCB0SDA/TB0TRG/OA0-/A2/Veref-)
MSP_A3_P1.3: U5.48(P1.3/UCB0SOMI/UCB0SCL/OA0+/A3) ; port MSP_A3_P1.3
MSP_CLK_P4.5: J9.20 U5.14(P4.5/UCB1CLK)
MSP_FGOUT_P2.1: J9.6 U5.29(P2.1/TB1.2/COMP1.O)
MSP_LED0_P2.2: D13.2(K) U5.28(P2.2/TB1CLK)
MSP_LED1_P2.2: D14.2(K) U5.27(P2.3/TB1TRG)
MSP_nFAULT_P3.3: J9.8 U5.44(P3.3/OA2+)
MSP_RX_P4.3: U3.5(RXD) U5.23(P4.3/UCA1TXD/UCA1SIMO/~{UCA1TXD})
MSP_SBWTCK: J7.4 U5.4(TEST/SBWTCK)
MSP_SBWTDIO/nRST: C48.1 J7.3 R16.1 S5.1 U5.5(~{RST}/NMI/SBWTDIO)
MSP_SIMO/SDA_P4.6: J9.22 U5.13(P4.6/UCB1SIMO/UCB1SDA)
MSP_SOMI/SCL_P4.7: J9.24 U5.12(P4.7/UCB1SOMI/UCB1SCL)
MSP_STE_P4.4: J9.18 U5.15(P4.4/UCB1STE)
MSP_TB0.1: U5.42(P5.1/TB2.2/MFM.TX/A9) ; port MSP_TB0.1
MSP_TX_P4.2: U3.1(TXD) U5.24(P4.2/UCA1RXD/UCA1SOMI/~{UCA1RXD})
MSP_XIN_P2.7: U5.8(P2.7/TB0CLK/XIN) Y1.1(In)
MSP_XOUT_P2.6: U5.9(P2.6/MCLK/XOUT) Y1.3(Out)
nFAULT: J9.7 ; port nFAULT
POT: U5.43(P5.0/TB2.1/MFM.RX/A8) ; port POT
SPEED/WAKE: J9.25 ; port SPEED/WAKE
SPEED_WAKE: J9.26 ; port SPEED_WAKE
NetD13_1: D13.1(A) R17.1
NetD14_1: D14.1(A) R18.1
NetJ5_1: J5.1(VBUS) L1.2

Not connected (* = marked no-connect by the designer): J9 3 4* 9 10 11 13 17* 19*; U3 2(~{DTR})* 3(~{RTS})* 6(~{RI})* 8(NC)* 9(~{DSR})* 10(~{DCD})* 11(~{CTS})* 12(CBUS4)* 13(CBUS2)* 14(CBUS3)* 19(~{RESET})* 22(CBUS1)* 23(CBUS0)* 24(NC)* 27(OSCI)* 28(OSCO)*; U4 1(IO1)*; U5 3(P1.0/UCB0STE/SMCLK/COMP0.0/A0/Veref+)* 10(P2.5/COMP1.0)* 11(P2.4/COMP1.1)* 16(P6.6/TB3CLK)* 17(P6.5/TB3.6)* 18(P6.4/TB3.5)* 19(P6.3/TB3.4)* 20(P6.2/TB3.3)* 21(P6.1/TB3.2)* 22(P6.0/TB3.1)* 25(P4.1/UCA1CLK)* 26(P4.0/UCA1STE/ISOTXD/ISORXD)* 30(P2.0/TB1.1/COMP0.O)* 31(P1.7/UCA0TXD/UCA0SIMO/TB0.2/TDO/OA1+/A7/VREF+)* 32(P1.6/UCA0RXD/UCA0SOMI/TB0.1/TDI/TCLK/OA1-/A6) 33(P1.5/UCA0CLK/TMS/OA1O/A5)* 34(P1.4/UCA0STE/TCK/A4)* 35(P3.7/OA3+)* 36(P3.6/OA3-)* 37(P3.5/OA3O)* 38(P3.4/SMCLK)* 39(P5.4)* 40(P5.3/TB2TRG/A11)* 41(P5.2/TB2CLK/A10)* 45(P3.2/OA2-) 46(P3.1/OA2O)* 47(P3.0/MCLK)*

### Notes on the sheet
- Micro USB Connector
- (near D4) FTDI REGULATOR
- (near L1) Changed to q200
- 5V_SEL
- MSP430 Reset / Pushbutton
- TX/RX LEDs
- (near R18) Use jumpers to connect J4 to GND, 3V3,
- SBWTDIO, and SBWTCK of MSP430 Launchpad.
- Remove jumpers from eZ-FET to MSP430 on Launchpad.
- (near U4) USB ESD Protection
- (near J8) 3.3V_SEL for MSP430
- (near U5) MSP430FR2355
- Signal Bank for connecting MSP430 + MCx8329A
- To MCx8329
- To MSP430FR2355
- (near Y1) CERAMIC RES 4.0000MHZ 39PF SMD
- TB1.2 inputs FGOUT
- or depopulate jumpers to use standalone MSP430 or MCx8329A.
- Populate jumpers to communicate onboard MSP430FR2355 to the MCx8329A

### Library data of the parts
C11 C16 C47 = CMP-0097294-1: as C7 on sheet MD067D_DRIVER
C46 = CMP-0007498-4: CAP, CERM, 4.7 uF, 10 V, +/- 20%, X7R, 0603; Manufacturer: MuRata; TaMin_C: -55°C; Polarized: N; SizeAreaWB_mm2: 4.68; Value1: Unknown; U/M: EA; Value: 4.7uF; TaMax_C: 125°C; SizeZ_mm: 1; SizeX_mm: 1.6; SizeY_mm: 0.8; Cap_Case: 0603; SizeArea_mm2: 1.28; AEC Category: Q200
C48 = CMP-0006826-4: CAP, CERM, 1000 pF, 16 V, +/- 10%, X7R, 0603; Manufacturer: Wurth Elektronik; TaMin_C: -55°C; Polarized: N; SizeAreaWB_mm2: 4.68; Value1: Unknown; U/M: EA; Value: 1000pF; TaMax_C: 125°C; SizeZ_mm: 1; SizeX_mm: 1.6; SizeY_mm: 0.8; Cap_Case: 0603; SizeArea_mm2: 1.28; AEC Category: Q200
C49 = CMP-0007696-2: CAP, CERM, 1 uF, 50 V, +/- 10%, X7R, 0805; Manufacturer: Wurth Elektronik; Polarized: N; CompType: Capacitor; Value: 1uF; U/M: EA; Cap_F: 1µF; Value1: Unknown; TaMin_C: -55°C; TaMax_C: 125°C; Cap_Case: 0805; SizeArea_mm2: 2.5; SizeAreaWB_mm2: 6.75; SizeX_mm: 2; SizeY_mm: 1.25; SizeZ_mm: 1.45; AEC Category: Q200
D4 = CMP-0028882-2: Diode, Schottky, 40 V, 0.75 A, AEC-Q101, SOD-323; Manufacturer: Infineon Technologies; Vf_V: 740mV; Value: 40V; Value1: 0.75A; Value2: 0.74V; Io_A: 750mA; TJmax_C: 150°C; AEC Category: Q101; AEC Qualified: Y; Green_Lifecycle: Not Set; Green_REACh: Incomplete; SizeArea_mm2: 3.645; SizeAreaWB_mm2: 8.695; SizeX_mm: 2.7; SizeY_mm: 1.35; SizeZ_mm: 1
D13 D14 = CMP-0121278-2: Red 625nm LED Indication - Discrete 2V 0603 (1608 Metric); Manufacturer: Wurth Electronics; SizeZ_mm: 0.8mm; Angle: 140°; Power_TotalModule: 78mW; LambdaP: 630nm; Tjmax_C: 125°C; Vr_V: 5V; AEC Qualified: No; Forward Current: 20mA; Led Orientation: Top View; Luminous Intensity: 530mcd
J5 = CMP-0055311-1: Receptacle, USB 2.0, Micro B, 5 Position, R/A, SMT; Manufacturer: Molex; CNHeader: FALSE; Current_A: 1.8A; Gender: Female; Voltage_V: 30V; Pitch_mm: 0.65; ContactFinish: Gold; CT: TRUE; Cert_UL: Y
J6 J8 = CMP-0054796-4: Header, 2.54 mm, 3x1, Gold, TH; Manufacturer: Wurth Elektronik; CNHeader: TRUE; CT: FALSE; Green_Lifecycle: Active; Green_REACh: Passed
J7 = CMP-0054798-2: Header, 2.54 mm, 4x1, Gold, TH; Manufacturer: Wurth Elektronik; Pitch_mm: 2.54; Gender: Male; Cert_UL: Y; Shrouded: N; Row_Count: 1
J9 = CMP-0075429-1: Header, 100mil, 16x2, Gold, TH; Manufacturer: Samtec; Pitch_mm: 2.54; Cert_VDE: N; Gender: Male; Cert_CSA: Y; Voltage_V: 550V; Green_REACh: Passed; Current_A: 6.3A; CT: False; Green_Lifecycle: Active; Row_Count: 2; CNHeader: True
L1 = CMP-0003154-2: Ferrite Bead, 110 ohm @ 100 MHz, 4.1 A, 0603; Manufacturer: Wurth Elektronik; SizeX_mm: 1.6; Value: 110 ohm; Value2: 4.1A; Value1: 0.0145 ohm; SizeZ_mm: 1; SizeY_mm: 0.8; SizeAreaWB_mm2: 4.68; SizeArea_mm2: 1.28; Ztyp@1GHz_Ohm: 51.875; ZTyp@100MHz_Ohm: 110
R16 = CMP-0025925-5: RES, 47 k, 5%, 0.1 W, 0603; Manufacturer: Yageo; Power_W: 100mW; TempCo: 100 ppm/C; Value_Code: 47k0; Value: 47k; EIA_Code: E24; SizeX_mm: 1.6; SizeY_mm: 0.8; SizeZ_mm: 1; Value2: 0.1W; SizeArea_mm2: 1.28; AEC Qualified: N; VDC_V: 75V; AEC Category: Q200; SizeAreaWB_mm2: 4.68
R17 R18 = CMP-0025924-5: RES, 470, 5%, 0.1 W, 0603; Manufacturer: Yageo; Power_W: 100mW; TempCo: 100 ppm/C; Value_Code: 470R; Value: 470; EIA_Code: E24; SizeX_mm: 1.6; SizeY_mm: 0.8; SizeZ_mm: 1; Value2: 0.1W; SizeArea_mm2: 1.28; AEC Qualified: N; VDC_V: 75V; AEC Category: Q200; SizeAreaWB_mm2: 4.68
S5 = CMP-0002196-2: Switch, Tactile, SPST, 12 V, SMD; PartNumber: 434121025816; Manufacturer: Wurth Elektronik; VDC_V: 12V; SwitchFunction: Off-On; PositionCount: 1; CurrentRating_mA: 50A
SH-J4-SH-J6 SH-J10-SH-J24 = CMP-0003761-2: as SH-J1 on sheet MD067D_DRIVER
TP41-TP45 = CMP-0055137-1: as TP1 on sheet MD067D_DRIVER
U3 = CMP-0121693-1: UART Interface IC USB Full Speed to Serial UART IC, Includes Oscillator and EEPROM, SSOP-28; Manufacturer: FTDI; SizeZ_mm: 2mm; AEC Qualified: No; Data Rate: 3Mbits/s; Interface: UART,USB; Max Supply Voltage: 5.25V; Min Supply Voltage: 1.8V; Nominal Supply Current: 7mA; Number Of Ports: 1; Standoff Height: 0.05mm; TaMax_C: +85°C; TaMin_C: -40°C; Usb Standard: USB 2.0
U4 = CMP-0043115-3: 4-Channel ESD Protection Array for High-Speed Data Interfaces, DRY0006A (USON-6); Manufacturer: Texas Instruments; IO Leakage Current(nA): 1; USB High Speed: TRUE; IO Capacitance(Typ)(pF): 1.6; Eco-Plan: Green (RoHS & no Sb/Br); IEC 61000-4-2 Contact(+/- kV): 8; Breakdown Voltage(Min)(V): 6; IEC 61000-4-2 Air-Gap(+/- kV): 12; AEC Category: Q200; AEC Qualified: N; CompType: IC; SizeAreaWB_mm2: 4.9; SizeArea_mm2: 1.45; SizeX_mm: 1.0; SizeZ_mm: 0.6; Rating: Catalog
U5 = CMP-0089204-1: CPU16 MSP430™ FRAM Microcontroller IC 16-Bit 24MHz 32KB (32K x 8) FRAM 48-LQFP (7x7); Manufacturer: Texas Instruments; Memory Type: OTHER; Data Bus Width: 16bits; Number Of Spi Channels: 4; Number Of I/Os: 44; Number Of Uart Channels: 2; AEC Qualified: No; Standoff Height: 0.05mm; Ram Size: 4KBytes; TaMin_C: -40°C; Core Architecture: RISC; Number Of Adc Channels: 12; SizeZ_mm: 1.6mm; Number Of A/D Converters: 1; Memory Size: 32KBytes; TaMax_C: +105°C; TJmax_C: +115°C; Interface: I2C,SPI,UART,USART,SCI,IrDA; Min Supply Voltage: 1.8V; Max Supply Voltage: 3.6V
Y1 = CMP-0084387-1: Resonator, 4 MHz, 39 pF, AEC-Q200 Grade 1, SMD; Manufacturer: MuRata; Load Capacitance: 39 pF; AEC Qualified: Y; TaMax_C: 125°C; AEC Category: Q200; SizeArea_mm2: 9; SizeZ_mm: 1.2; Frequency_Fixed: 4MHz; SizeAreaWB_mm2: 16.5; SizeY_mm: 2; SizeX_mm: 4.5; TaMin_C: -40°C; AEC Grade: 1

## Sheet MD067D_HARDWARE.SchDoc
size 431 x 279 mm; Date: Not shown in title block; ApprovedBy: Not shown in title block; CheckedBy: Not shown in title block; Author: Not shown in title block; CompanyName: Not shown in title block; Engineer: Not shown in title block; Organization: Not shown in title block; Address1: Not shown in title block; Address2: Not shown in title block; Address3: Not shown in title block; Address4: Not shown in title block; DocumentNumber: 5; Revision: Use project parameter SCH_Rev; SheetNumber: 5; SheetTotal: 5; PageSetup: Record=PageOptions¦CenterHorizontal=True¦CenterVertical=True¦PrintScale=1.00¦XCorrection=1.00¦YCorrection=1.00¦PrintKind=0¦BorderSize=5000000¦LeftOffset=0¦BottomOffset=0¦Orientation=2¦PaperLength=1000¦PaperWidth=1000¦Scale=100¦PaperSource=15¦PrintQuality=600¦MediaType=1¦DitherType=10¦PaperKind=Letter¦PrintScaleMode=1
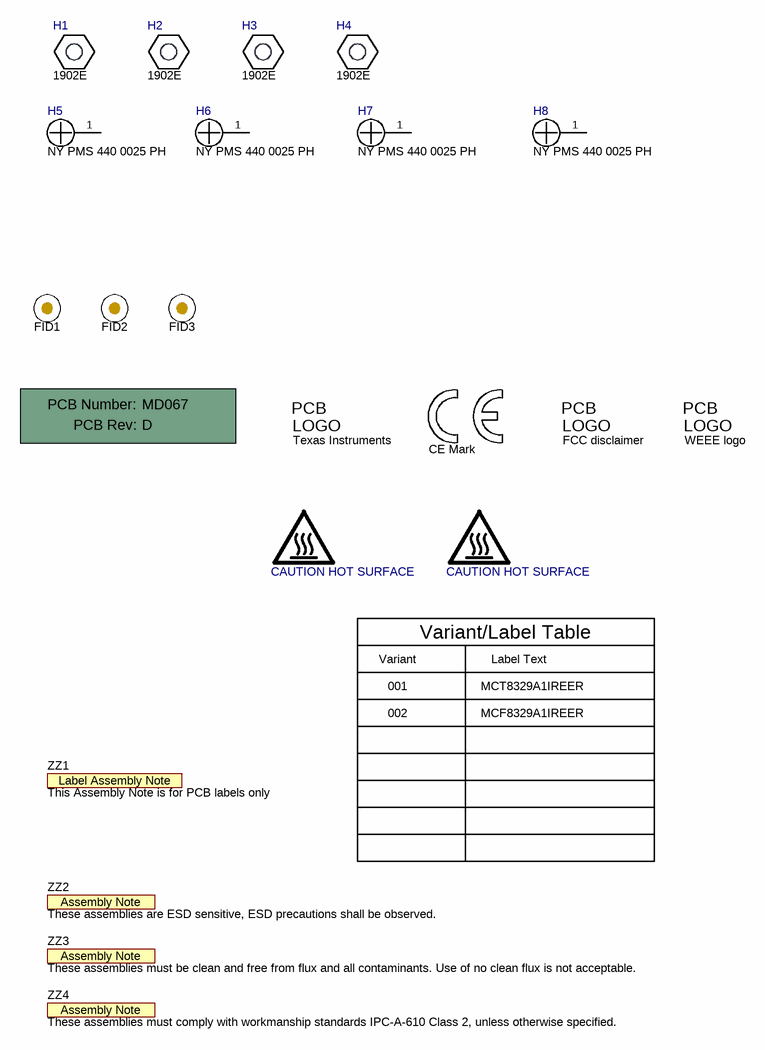
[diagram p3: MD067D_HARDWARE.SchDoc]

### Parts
!PCB1  Printed Circuit Board  (value not drawn)  (mechanical)
FID1  Fiducial  [Fiducial10-20]  (value not drawn)
FID2  Fiducial  [Fiducial10-20]  (value not drawn)
FID3  Fiducial  [Fiducial10-20]  (value not drawn)
H1  1902E  [Keystone_1902E]
H2  1902E  [Keystone_1902E]
H3  1902E  [Keystone_1902E]
H4  1902E  [Keystone_1902E]
H5  NY PMS 440 0025 PH  [NY PMS 440 0025 PH]
H6  NY PMS 440 0025 PH  [NY PMS 440 0025 PH]
H7  NY PMS 440 0025 PH  [NY PMS 440 0025 PH]
H8  NY PMS 440 0025 PH  [NY PMS 440 0025 PH]
Logo1  CE Mark  [CE_Mark_5mm]  (no BOM)
Logo2  Texas Instruments  [TI_Stacked_Overlay_Small]  (no BOM)
Logo3  FCC disclaimer  [FCC_disclaimer]  (no BOM)
Logo4  WEEE logo  [WEEE_Minimum]  (no BOM)
LOGO5  CAUTION HOT SURFACE  [IEC_HotSurface_Small]  (no BOM)
LOGO6  CAUTION HOT SURFACE  [IEC_HotSurface_Small]  (no BOM)
ZZ1  This Assembly Note is for PCB labels only  [AssemblyNoteLabel]  (no BOM)
ZZ2  These assemblies are ESD sensitive, ESD precautions shall be observed.  [AssemblyNote]  (no BOM)
ZZ3  These assemblies must be clean and free from flux and all contaminants. Use of no clean flux is not acceptable.  [AssemblyNote]  (no BOM)
ZZ4  These assemblies must comply with workmanship standards IPC-A-610 Class 2, unless otherwise specified.  [AssemblyNote]  (no BOM)

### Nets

Not connected (* = marked no-connect by the designer): H5 1; H6 1; H7 1; H8 1

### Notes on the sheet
- Variant
- Variant/Label Table
- Label Text
- 001
- 002
- MCT8329A1IREER
- MCF8329A1IREER

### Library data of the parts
!PCB1 = CMP-0003618-2: Manufacturer: Any; PartNumber: MD067
FID1-FID3 = CMP-0077181-1: Fiducial mark.  There is nothing to buy or mount.
H1-H4 = CMP-0003611-1: Standoff, Hex, 1"L #4-40 Nylon; Manufacturer: Keystone; CompType: Hardware
H5-H8 = CMP-0003617-1: Machine Screw, Round, #4-40 x 1/4, Nylon, Philips panhead; Manufacturer: B&F Fastener Supply; CompType: Hardware
Logo1 = CMP-0074844-1: SymbolCreator: a0412235
Logo2 = CMP-0074838-1: Texas Instrument Corporate Signature; SymbolCreator: a0412235; Lib Reference: TI_Logo; Library Reference: Logo
Logo3 = CMP-0074847-1: FCC_disclaimer; Library Reference: Logo
Logo4 = CMP-0074769-1
LOGO5 LOGO6 = CMP-0074837-1: IEC 61010-1 Hot Surface Warning; SymbolCreator: a0412235
ZZ1 = CMP-0003616-3
ZZ2 = CMP-0077236-1
ZZ3 = CMP-0077237-1
ZZ4 = CMP-0077238-1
